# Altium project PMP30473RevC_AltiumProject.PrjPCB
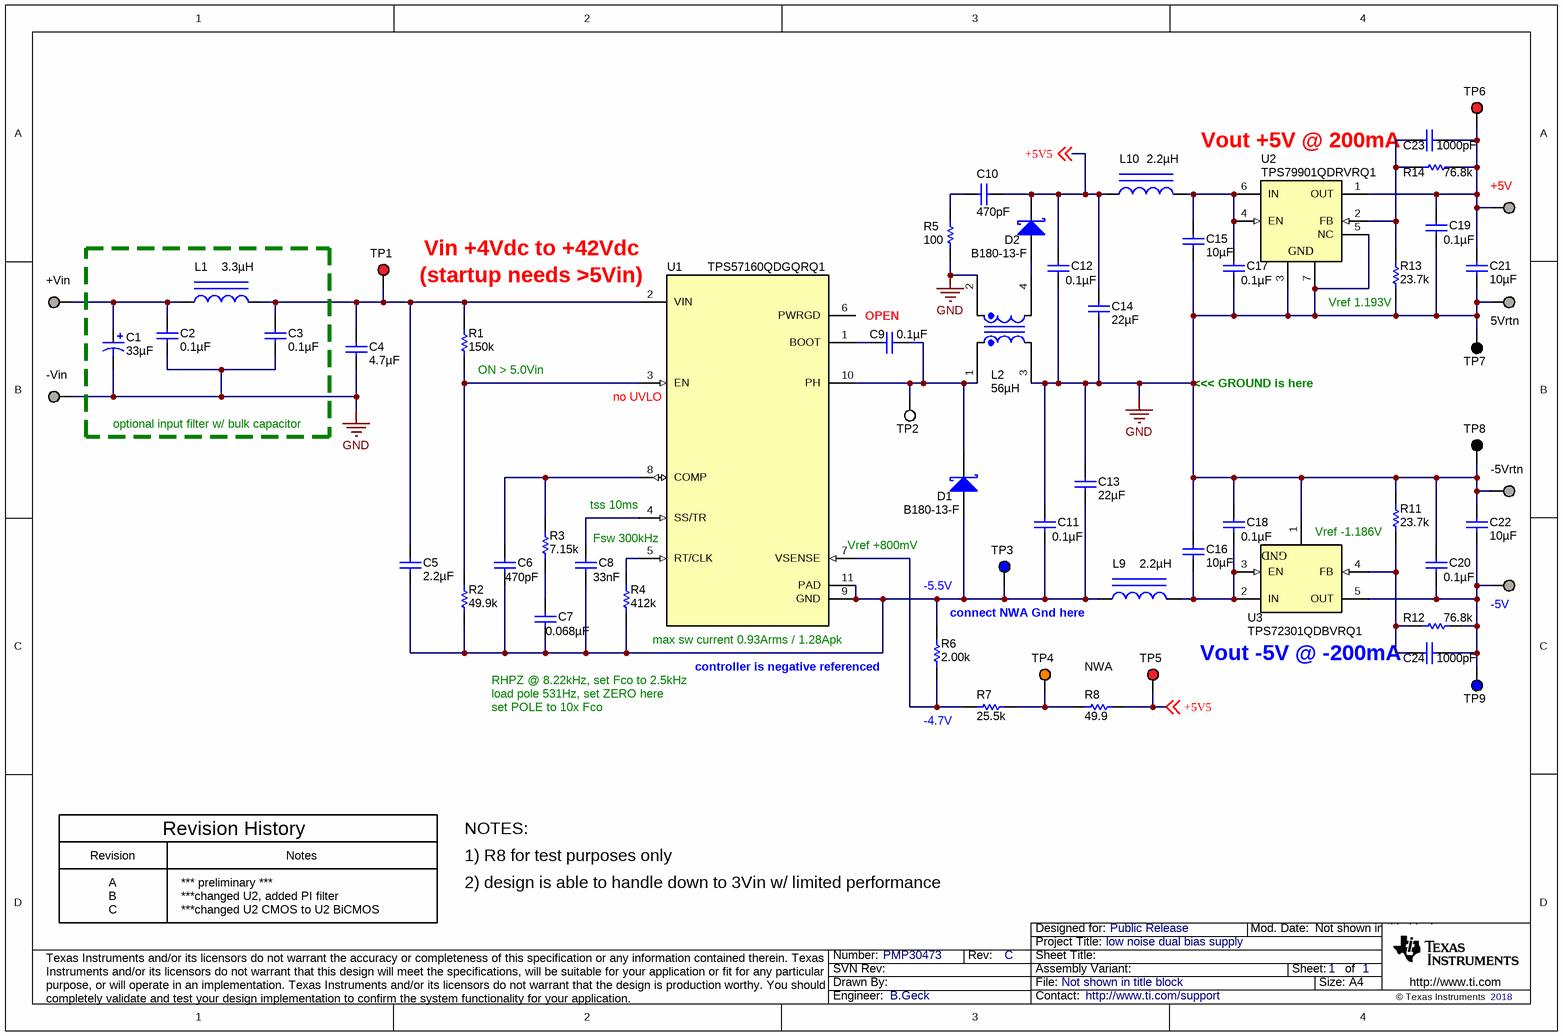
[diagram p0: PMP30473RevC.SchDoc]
CopyrightYear: 2018; PCB_Layout: B.Geck; PCB_Rev: C; PRJ_Customer: Public Release; PRJ_Engineer: B.Geck; PRJ_Number: PMP30473; PRJ_Title: low noise dual bias supply; SCH_Rev: C; TechSupport: http://www.ti.com/support
1 sheet, 60 parts. Net scope: global (net labels, ports and power ports of the same name join across sheets).
Board file: PMP30473RevC_board.PcbDoc

## Sheet PMP30473RevC.SchDoc
size A4; Date: Not shown in title block; ApprovedBy: Not shown in title block; CheckedBy: Not shown in title block; Author: Not shown in title block; CompanyName: Not shown in title block; Engineer: Not shown in title block; Organization: Not shown in title block; Address1: Not shown in title block; Address2: Not shown in title block; Address3: Not shown in title block; Address4: Not shown in title block; DocumentNumber: 1; Revision: Use project parameter SCH_Rev; SheetNumber: 1; SheetTotal: 1; PageSetup: Record=PageOptions¦CenterHorizontal=True¦CenterVertical=True¦PrintScale=0.70¦XCorrection=1.00¦YCorrection=1.00¦PrintKind=0¦BorderSize=5000000¦LeftOffset=0¦BottomOffset=0¦Orientation=2¦PaperLength=1000¦PaperWidth=1000¦Scale=100¦PaperSource=15¦PrintQuality=600¦MediaType=1¦DitherType=10¦PaperKind=A4¦PrintScaleMode=1

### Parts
5Vrtn  Suggest using a net name here  [Keystone1502-2]  (value not drawn)
+5V  Suggest using a net name here  [Keystone1502-2]  (value not drawn)
+Vin  Suggest using a net name here  [Keystone1502-2]  (value not drawn)
-5V  Suggest using a net name here  [Keystone1502-2]  (value not drawn)
-5Vrtn  Suggest using a net name here  [Keystone1502-2]  (value not drawn)
-Vin  Suggest using a net name here  [Keystone1502-2]  (value not drawn)
C1  ValueDisplayed: 33µF  [SM_RADIAL_6.3BMM]  (hidden comment: EEHZC1H330XP)
C2  ValueDisplayed: 0.1µF  [0603]  (hidden comment: GRM188R71H104KA93D)
C3  ValueDisplayed: 0.1µF  [0603]  (hidden comment: GRM188R71H104KA93D)
C4  ValueDisplayed: 4.7µF  [1206_180]  (hidden comment: GRM31CR71H475KA12L)
C5  ValueDisplayed: 2.2µF  [1206_190]  (hidden comment: GRM31CR72A225KA73L)
C6  ValueDisplayed: 470pF  [0603]  (hidden comment: GRM188R71H471KA01D)
C7  ValueDisplayed: 0.068µF  [0603]  (hidden comment: GRM188R71E683KA01D)
C8  ValueDisplayed: 33nF  [0603]  (hidden comment: GRM188R71E333KA01D)
C9  ValueDisplayed: 0.1µF  [0603]  (hidden comment: GRM188R71E104KA01D)
C10  ValueDisplayed: 470pF  [0603]  (hidden comment: GRM188R72A471KA01D)
C11  ValueDisplayed: 0.1µF  [0603]  (hidden comment: GRM188R71H104KA93D)
C12  ValueDisplayed: 0.1µF  [0603]  (hidden comment: GRM188R71H104KA93D)
C13  ValueDisplayed: 22µF  [1206_180]  (hidden comment: GRM31CR71A226KE15L)
C14  ValueDisplayed: 22µF  [1206_180]  (hidden comment: GRM31CR71A226KE15L)
C15  ValueDisplayed: 10µF  [0805_HV]  (hidden comment: GRM21BR71A106KE51K)
C16  ValueDisplayed: 10µF  [0805_HV]  (hidden comment: GRM21BR71A106KE51K)
C17  ValueDisplayed: 0.1µF  [0603]  (hidden comment: GRM188R71H104KA93D)
C18  ValueDisplayed: 0.1µF  [0603]  (hidden comment: GRM188R71H104KA93D)
C19  ValueDisplayed: 0.1µF  [0603]  (hidden comment: GRM188R71H104KA93D)
C20  ValueDisplayed: 0.1µF  [0603]  (hidden comment: GRM188R71H104KA93D)
C21  ValueDisplayed: 10µF  [0805_HV]  (hidden comment: GRM21BR71A106KE51K)
C22  ValueDisplayed: 10µF  [0805_HV]  (hidden comment: GRM21BR71A106KE51K)
C23  ValueDisplayed: 1000pF  [0603]  (hidden comment: GRM188R71E102KA01D)
C24  ValueDisplayed: 1000pF  [0603]  (hidden comment: GRM188R71E102KA01D)
D1  B180-13-F  [SMA]
D2  B180-13-F  [SMA]
L1  ValueDisplayed: 3.3µH  [LPS4012]  (hidden comment: LPS4012-332MLB)
L2  ValueDisplayed: 56µH  [MSD1260]  (hidden comment: MSD1260-563ML)
L9  ValueDisplayed: 2.2µH  [0805_HV]  (hidden comment: LQM21PN2R2MGS)
L10  ValueDisplayed: 2.2µH  [0805_HV]  (hidden comment: LQM21PN2R2MGS)
R1  ValueDisplayed: 150k  [0603]  (hidden comment: CRCW0603150KFKEA)
R2  ValueDisplayed: 49.9k  [0603]  (hidden comment: CRCW060349K9FKEA)
R3  ValueDisplayed: 7.15k  [0603]  (hidden comment: CRCW06037K15FKEA)
R4  ValueDisplayed: 412k  [0603]  (hidden comment: CRCW0603412KFKEA)
R5  ValueDisplayed: 100  [0603]  (hidden comment: CRCW0603100RJNEA)
R6  ValueDisplayed: 2.00k  [0603]  (hidden comment: CRCW06032K00FKEA)
R7  ValueDisplayed: 25.5k  [0603]  (hidden comment: CRCW060325K5FKEA)
R8  ValueDisplayed: 49.9  [0603]  (hidden comment: CRCW060349R9FKEA)
R11  ValueDisplayed: 23.7k  [0603]  (hidden comment: CRCW060323K7FKEA)
R12  ValueDisplayed: 76.8k  [0603]  (hidden comment: CRCW060376K8FKEA)
R13  ValueDisplayed: 23.7k  [0603]  (hidden comment: CRCW060323K7FKEA)
R14  ValueDisplayed: 76.8k  [0603]  (hidden comment: CRCW060376K8FKEA)
TP1  5000  [Keystone5000]  (value not drawn)
TP2  5002  [Keystone5002]  (value not drawn)
TP3  5117  [Keystone5117]  (value not drawn)
TP4  5003  [Keystone5003]  (value not drawn)
TP5  5000  [Keystone5000]  (value not drawn)
TP6  5000  [Keystone5000]  (value not drawn)
TP7  5001  [Keystone5001]  (value not drawn)
TP8  5001  [Keystone5001]  (value not drawn)
TP9  5117  [Keystone5117]  (value not drawn)
U1  TPS57160QDGQRQ1  [DGQ0010D_N]
U2  TPS79901QDRVRQ1  [DRV0006A]
U3  TPS72301QDBVRQ1  [DBV0005A_N]

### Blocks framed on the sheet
optional input filter w/ bulk capacitor: C1-C3 L1

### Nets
GND: 5Vrtn.1 -5Vrtn.1 -Vin.1 C1.2(-) C2.2 C3.2 C4.2 C11.1 C12.2 C13.1 C14.2 C15.2 C16.1 C17.2 C18.1 C19.2 C20.1 C21.2 C22.1 L2.2 L2.3 R5.1 R11.2 R13.1 TP7.1 TP8.1 U2.3(GND) U2.5(NC) U2.7(GND) U3.1(GND)
+5V5: C10.1 C12.1 C14.1 D2.1(K) L10.1 R8.1 TP5.1 ; off-sheet +5V5
Net+5V_1: +5V.1 C19.1 C21.1 C23.1 R14.1 TP6.1 U2.1(OUT)
Net+Vin_1: +Vin.1 C1.1(+) C2.1 L1.1
Net-5V_1: -5V.1 C20.2 C22.2 C24.1 R12.1 TP9.1 U3.5(OUT)
NetC3_1: C3.1 C4.1 C5.1 L1.2 R1.2 TP1.1 U1.2(VIN)
NetC5_2: C5.2 C6.2 C7.2 C8.2 C11.2 C13.2 D1.2(A) L9.1 R2.1 R4.1 R6.2 TP3.1 U1.9(GND) U1.11(PAD)
NetC6_1: C6.1 R3.2 U1.8(COMP)
NetC7_1: C7.1 R3.1
NetC8_1: C8.1 U1.4(SS/TR)
NetC9_1: C9.1 D1.1(K) L2.1 TP2.1 U1.10(PH)
NetC9_2: C9.2 U1.1(BOOT)
NetC10_2: C10.2 R5.2
NetC15_1: C15.1 C17.1 L10.2 U2.4(EN) U2.6(IN)
NetC16_2: C16.2 C18.2 L9.2 U3.2(IN) U3.3(EN)
NetC23_2: C23.2 R13.2 R14.2 U2.2(FB)
NetC24_2: C24.2 R11.1 R12.2 U3.4(FB)
NetD2_2: D2.2(A) L2.4
NetR1_1: R1.1 R2.2 U1.3(EN)
NetR4_2: R4.2 U1.5(RT/CLK)
NetR6_1: R6.1 R7.1 U1.7(VSENSE)
NetR7_2: R7.2 R8.2 TP4.1

Not connected (* = marked no-connect by the designer): U1 6(PWRGD)

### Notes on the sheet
- Vout +5V @ 200mA
- Vin +4Vdc to +42Vdc
- (startup needs >5Vin)
- (near C9) OPEN
- (near R13) Vref 1.193V
- (near R1) ON > 5.0Vin
- <<< GROUND is here
- (near U1) no UVLO !
- (near U1) tss 10ms
- (near U1) Fsw 300kHz
- (near U1) Vref +800mV
- -5.5V
- Vref -1.186V
- max sw current 0.93Arms / 1.28Apk
- connect NWA Gnd here
- Vout -5V @ -200mA
- load pole 531Hz, set ZERO here
- set POLE to 10x Fco
- RHPZ @ 8.22kHz, set Fco to 2.5kHz
- controller is negative referenced
- (near R7) -4.7V
- NWA
- Revision
- Revision History
- Notes
- NOTES:
- 1) R8 for test purposes only
- A
- B
- C
- *** preliminary ***
- ***changed U2, added PI filter
- ***changed U2 CMOS to U2 BiCMOS
- 2) design is able to handle down to 3Vin w/ limited performance

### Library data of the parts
5Vrtn +5V +Vin -5V -5Vrtn -Vin = 1502-2: Terminal, Turret, TH, Double; Manufacturer: Keystone; CompType: Turret Terminal; Green_Lifecycle: Active; Green_REACh: Passed
C1 = EEHZC1H330XP: CAP, Polymer Hybrid, 33 µF, 50 V,+/- 20%, 40 ohm, 6.3x7.7 SMD; Manufacturer: Panasonic; Polarized: Y; CompType: Capacitor; Value: 33uF; U/M: EA; Cap_F: 0.000033; Tolerance_%: 20; Value1: 40 ohm; VDC_V: 50; Value2: 50V; ESR_ohm: 40; IRMS_A: 1.1; TaMin_C: -55; TaMax_C: 125; SizeAreaWB_mm2: 79.98; SizeArea_mm2: 48.18; SizeX_mm: 7.3; SizeY_mm: 6.6; SizeZ_mm: 7.7; AEC Category: Q200; Green_Lifecycle: Active; Green_REACh: Passed
C2 C3 = GRM188R71H104KA93D: CAP, CERM, 0.1 µF, 50 V,+/- 10%, X7R, 0603; Manufacturer: MuRata; Polarized: N; CompType: Capacitor; Value: 0.1uF; U/M: EA; Cap_F: 0.0000001; Tolerance_%: 10; VDC_V: 50; Value2: 50V; TaMin_C: -55; TaMax_C: 125; SizeArea_mm2: 1.28; SizeAreaWB_mm2: 4.68; SizeX_mm: 1.6; SizeY_mm: 0.8; SizeZ_mm: 1; AEC Category: Q200; Green_Lifecycle: Active; Green_REACh: Passed
C4 = GRM31CR71H475KA12L: CAP, CERM, 4.7 µF, 50 V,+/- 10%, X7R, 1206; Manufacturer: MuRata; Polarized: N; CompType: Capacitor; Value: 4.7uF; U/M: EA; Cap_F: 0.0000047; Tolerance_%: 10; VDC_V: 50; Value2: 50V; TaMin_C: -55; TaMax_C: 125; Cap_Case: 1206; SizeArea_mm2: 5.12; SizeAreaWB_mm2: 10.92; SizeX_mm: 3.2; SizeY_mm: 1.6; SizeZ_mm: 1.8; AEC Category: Q200; Green_Lifecycle: Active; Green_REACh: Passed
C5 = GRM31CR72A225KA73L: CAP, CERM, 2.2 µF, 100 V,+/- 10%, X7R, 1206; Manufacturer: MuRata; Polarized: N; CompType: Capacitor; Value: 2.2uF; U/M: EA; Cap_F: 0.0000022; Tolerance_%: 10; VDC_V: 100; Value2: 100V; TaMin_C: -55; TaMax_C: 125; Cap_Case: 1206; SizeArea_mm2: 5.12; SizeAreaWB_mm2: 10.92; SizeX_mm: 3.2; SizeY_mm: 1.6; SizeZ_mm: 1.9; AEC Category: Q200; Green_Lifecycle: Active; Green_REACh: Passed
C6 = GRM188R71H471KA01D: CAP, CERM, 470 pF, 50 V,+/- 10%, X7R, 0603; Manufacturer: MuRata; Polarized: N; CompType: Capacitor; Value: 470pF; U/M: EA; Cap_F: 0.00000000047; Tolerance_%: 10; VDC_V: 50; Value2: 50V; TaMin_C: -55; TaMax_C: 125; SizeArea_mm2: 1.28; SizeAreaWB_mm2: 4.68; SizeX_mm: 1.6; SizeY_mm: 0.8; SizeZ_mm: 1; AEC Category: Q200; Green_Lifecycle: Active; Green_REACh: Passed
C7 = GRM188R71E683KA01D: CAP, CERM, 0.068 µF, 25 V,+/- 10%, X7R, 0603; Manufacturer: MuRata; Polarized: N; CompType: Capacitor; Value: 0.068uF; U/M: EA; Cap_F: 0.000000068; Tolerance_%: 10; VDC_V: 25; Value2: 25V; TaMin_C: -55; TaMax_C: 125; SizeArea_mm2: 1.28; SizeAreaWB_mm2: 4.68; SizeX_mm: 1.6; SizeY_mm: 0.8; SizeZ_mm: 1; AEC Category: Q200; Green_Lifecycle: Active; Green_REACh: Passed
C8 = GRM188R71E333KA01D: CAP, CERM, 0.033 µF, 25 V, +/- 10%, X7R, 0603; Manufacturer: MuRata; Polarized: N; CompType: Capacitor; Value: 0.033uF; U/M: EA; Cap_F: 0.000000033; Tolerance_%: 10; Value1: Unknown; VDC_V: 25; Value2: 25V; TaMin_C: -55; TaMax_C: 125; SizeArea_mm2: 1.28; SizeAreaWB_mm2: 4.68; SizeX_mm: 1.6; SizeY_mm: 0.8; SizeZ_mm: 1; AEC Category: Q200
C9 = GRM188R71E104KA01D: CAP, CERM, 0.1 µF, 25 V, +/- 10%, X7R, 0603; Manufacturer: MuRata; Polarized: N; CompType: Capacitor; Value: 0.1uF; U/M: EA; Cap_F: 0.0000001; Tolerance_%: 10; Value1: Unknown; VDC_V: 25; Value2: 25V; TaMin_C: -55; TaMax_C: 125; SizeArea_mm2: 1.28; SizeAreaWB_mm2: 4.68; SizeX_mm: 1.6; SizeY_mm: 0.8; SizeZ_mm: 1; AEC Category: Q200
C10 = GRM188R72A471KA01D: CAP, CERM, 470 pF, 100 V,+/- 10%, X7R, 0603; Manufacturer: MuRata; Polarized: N; CompType: Capacitor; Value: 470pF; U/M: EA; Cap_F: 0.00000000047; Tolerance_%: 10; VDC_V: 100; Value2: 100V; TaMin_C: -55; TaMax_C: 125; SizeArea_mm2: 1.28; SizeAreaWB_mm2: 4.68; SizeX_mm: 1.6; SizeY_mm: 0.8; SizeZ_mm: 1; AEC Category: Q200
C11 C12 C17-C20 = GRM188R71H104KA93D: CAP, CERM, 0.1 µF, 50 V, +/- 10%, X7R, 0603; Manufacturer: MuRata; Polarized: N; CompType: Capacitor; Value: 0.1uF; U/M: EA; Cap_F: 0.0000001; Tolerance_%: 10; Value1: Unknown; VDC_V: 50; Value2: 50V; TaMin_C: -55; TaMax_C: 125; SizeArea_mm2: 1.28; SizeAreaWB_mm2: 4.68; SizeX_mm: 1.6; SizeY_mm: 0.8; SizeZ_mm: 1; AEC Category: Q200
C13 C14 = GRM31CR71A226KE15L: CAP, CERM, 22 µF, 10 V,+/- 10%, X7R, 1206; Manufacturer: MuRata; Polarized: N; CompType: Capacitor; Value: 22uF; U/M: EA; Cap_F: 0.000022; Tolerance_%: 10; Value2: 10V; TaMin_C: -55; TaMax_C: 125; Cap_Case: 1206; SizeArea_mm2: 5.12; SizeAreaWB_mm2: 10.92; SizeX_mm: 3.2; SizeY_mm: 1.6; SizeZ_mm: 1.8; AEC Category: Q200; Green_Lifecycle: Active; Green_REACh: Passed
C15 C16 C21 C22 = GRM21BR71A106KE51K: CAP, CERM, 10 µF, 10 V,+/- 10%, X7R, 0805; Manufacturer: MuRata; Polarized: N; CompType: Capacitor; Value: 10uF; U/M: EA; Cap_F: 0.00001; Tolerance_%: 10; Value2: 10V; TaMin_C: -55; TaMax_C: 125; Cap_Case: 0805; SizeArea_mm2: 2.5; SizeAreaWB_mm2: 6.75; SizeX_mm: 2; SizeY_mm: 1.25; SizeZ_mm: 1.45; AEC Category: Q200; Green_Lifecycle: Active; Green_REACh: Passed
C23 C24 = GRM188R71E102KA01D: CAP, CERM, 1000 pF, 25 V,+/- 10%, X7R, 0603; Manufacturer: MuRata; Polarized: N; CompType: Capacitor; Value: 1000pF; U/M: EA; Cap_F: 0.000000001; Tolerance_%: 10; VDC_V: 25; Value2: 25V; TaMin_C: -55; TaMax_C: 125; SizeArea_mm2: 1.28; SizeAreaWB_mm2: 4.68; SizeX_mm: 1.6; SizeY_mm: 0.8; SizeZ_mm: 1; AEC Category: Q200; Green_Lifecycle: Active; Green_REACh: Passed
D1 D2 = B180-13-F: Diode, Schottky, 80 V, 1 A, SMA; Manufacturer: Diodes Inc.; U/M: EA; Vf_V: 0.79; Value: 80V; Value1: 1A; Value2: 0.79V; Io_A: 1; Vr_V: 80; TJmax_C: 150; RJC_CperW: 25; SizeAreaWB_mm2: 37.3428; SizeArea_mm2: 16.3228; SizeX_mm: 5.59; SizeY_mm: 2.92; SizeZ_mm: 2.87; AEC Category: Q101; Green_Lifecycle: Not Set; Green_REACh: Incomplete
L1 = LPS4012-332MLB: Inductor, Shielded Drum Core, Ferrite, 3.3 µH, 1.4 A, 0.1 ohm, SMD; Manufacturer: Coilcraft; Value: 3.3uH; Ind_H: 3.3E-6; Imax_A: 1.4; Irms: 2A @ 40C rise; Isat: 1.4A @ 30% inductance drop; DCR_ohm: 0.1; Value1: 0.1 ohm; Value2: 1.4A; SizeAreaWB_mm2: 25; SizeArea_mm2: 16; SizeX_mm: 4; SizeZ_mm: 1.2; AEC Category: Q200; Green_Lifecycle: Not Set; Green_REACh: Incomplete
L2 = MSD1260-563ML: Coupled inductor, 56 µH, 3.07 A, 0.198 ohm, AEC-Q200 Grade 3, TH; Manufacturer: Coilcraft; SymbolCreator: a0412235; SizeAreaWB_mm2: 204.49; SizeArea_mm2: 151.29; SizeX_mm: 12.3; SizeZ_mm: 6.2; Value: 56uH; Ind_H: 56.0E-6; DCR_ohm: 0.198; AEC Category: Q200; AEC Qualified: Y; AEC Grade: 3
L9 L10 = LQM21PN2R2MGS: Inductor, Multilayer, Ferrite, 2.2 µH, 0.95 A, 0.18 ohm, SMD; Manufacturer: MuRata; Value: 2.2uH; Ind_H: 2.2E-6; Imax_A: 0.95; DCR_ohm: 0.18; Value2: 0.95A; SizeAreaWB_mm2: 6.75; SizeArea_mm2: 2.5; SizeX_mm: 2; SizeY_mm: 1.25; SizeZ_mm: 1.45; AEC Category: Q200; Green_Lifecycle: Active; Green_REACh: Passed
R1 = CRCW0603150KFKEA: RES, 150 k, 1%, 0.1 W, 0603; Manufacturer: Vishay-Dale; CompType: Resistor; Value: 150k; Res_ohm: 150000; Tolerance_%: 1; Power_W: 0.1; Value2: 0.1W; VDC_V: 75; TempCo: 100 ppm/C; SizeArea_mm2: 1.28; SizeX_mm: 1.6; SizeY_mm: 0.8; EIA_Code: E96; U/M: EA; AEC Category: Q200; Green_Lifecycle: Active; Green_REACh: Passed
R2 = CRCW060349K9FKEA: RES, 49.9 k, 1%, 0.1 W, 0603; Manufacturer: Vishay-Dale; CompType: Resistor; Value: 49.9k; Res_ohm: 49900; Value_Code: 49k9; Tolerance_%: 1; Power_W: 0.1; Value2: 0.1W; VDC_V: 75; TempCo: 100 ppm/C; SizeArea_mm2: 1.28; SizeX_mm: 1.6; SizeY_mm: 0.8; EIA_Code: E96; U/M: EA; AEC Category: Q200; Green_Lifecycle: Active; Green_REACh: Passed
R3 = CRCW06037K15FKEA: RES, 7.15 k, 1%, 0.1 W, 0603; Manufacturer: Vishay-Dale; CompType: Resistor; Value: 7.15k; Res_ohm: 7150; Value_Code: 7k15; Tolerance_%: 1; Power_W: 0.1; Value2: 0.1W; VDC_V: 75; TempCo: 100 ppm/C; SizeArea_mm2: 1.28; SizeX_mm: 1.6; SizeY_mm: 0.8; EIA_Code: E96; U/M: EA; AEC Category: Q200; Green_Lifecycle: Active; Green_REACh: Passed
R4 = CRCW0603412KFKEA: RES, 412 k, 1%, 0.1 W, 0603; Manufacturer: Vishay-Dale; CompType: Resistor; Value: 412k; Res_ohm: 412000; Tolerance_%: 1; Power_W: 0.1; Value2: 0.1W; VDC_V: 75; TempCo: 100 ppm/C; SizeArea_mm2: 1.28; SizeX_mm: 1.6; SizeY_mm: 0.8; EIA_Code: E96; U/M: EA; AEC Category: Q200
R5 = CRCW0603100RJNEA: RES, 100, 5%, 0.1 W, 0603; Manufacturer: Vishay-Dale; CompType: Resistor; Value: 100; Value_Code: 100R; Tolerance_%: 5; Power_W: 0.1; Value2: 0.1W; VDC_V: 75; TempCo: 200 ppm/C; SizeArea_mm2: 1.28; SizeX_mm: 1.6; SizeY_mm: 0.8; SizeZ_mm: 1; EIA_Code: E24; U/M: EA; AEC Category: Q200; Green_Lifecycle: Active; Green_REACh: Passed
R6 = CRCW06032K00FKEA: RES, 2.00 k, 1%, 0.1 W, 0603; Manufacturer: Vishay-Dale; CompType: Resistor; Value: 2.00k; Res_ohm: 2000; Value_Code: 2k00; Tolerance_%: 1; Power_W: 0.1; Value2: 0.1W; VDC_V: 75; TempCo: 100 ppm/C; SizeArea_mm2: 1.28; SizeX_mm: 1.6; SizeY_mm: 0.8; EIA_Code: E96; U/M: EA; AEC Category: Q200; Green_Lifecycle: Active; Green_REACh: Passed
R7 = CRCW060325K5FKEA: RES, 25.5 k, 1%, 0.1 W, 0603; Manufacturer: Vishay-Dale; CompType: Resistor; Value: 25.5k; Res_ohm: 25500; Value_Code: 25k5; Tolerance_%: 1; Power_W: 0.1; Value2: 0.1W; VDC_V: 75; TempCo: 100 ppm/C; SizeArea_mm2: 1.28; SizeX_mm: 1.6; SizeY_mm: 0.8; EIA_Code: E96; U/M: EA; AEC Category: Q200; Green_Lifecycle: Active; Green_REACh: Passed
R8 = CRCW060349R9FKEA: RES, 49.9, 1%, 0.1 W, 0603; Manufacturer: Vishay-Dale; CompType: Resistor; Value: 49.9; Value_Code: 49R9; Tolerance_%: 1; Power_W: 0.1; Value2: 0.1W; VDC_V: 75; TempCo: 100 ppm/C; SizeArea_mm2: 1.28; SizeX_mm: 1.6; SizeY_mm: 0.8; EIA_Code: E96; U/M: EA; AEC Category: Q200
R11 R13 = CRCW060323K7FKEA: RES, 23.7 k, 1%, 0.1 W, 0603; Manufacturer: Vishay-Dale; CompType: Resistor; Value: 23.7k; Res_ohm: 23700; Value_Code: 23k7; Tolerance_%: 1; Power_W: 0.1; Value2: 0.1W; VDC_V: 75; TempCo: 100 ppm/C; SizeArea_mm2: 1.28; SizeX_mm: 1.6; SizeY_mm: 0.8; EIA_Code: E96; U/M: EA; AEC Category: Q200
R12 R14 = CRCW060376K8FKEA: RES, 76.8 k, 1%, 0.1 W, 0603; Manufacturer: Vishay-Dale; CompType: Resistor; Value: 76.8k; Res_ohm: 76800; Value_Code: 76k8; Tolerance_%: 1; Power_W: 0.1; Value2: 0.1W; VDC_V: 75; TempCo: 100 ppm/C; SizeArea_mm2: 1.28; SizeX_mm: 1.6; SizeY_mm: 0.8; EIA_Code: E96; U/M: EA; AEC Category: Q200; Green_Lifecycle: Active; Green_REACh: Passed
TP1 TP5 TP6 = 5000: Test Point, Miniature, Red, TH; Manufacturer: Keystone; CompType: Test Point Loop; U/M: EA
TP2 = 5002: Test Point, Miniature, White, TH; Manufacturer: Keystone; CompType: Test Point Loop; ContactFinish: Silver; Green_Lifecycle: Active; Green_REACh: Passed
TP3 TP9 = 5117: Test Point, Miniature, Blue, TH; Manufacturer: Keystone; CompType: Test Point Loop; U/M: EA; ContactFinish: Silver; Green_Lifecycle: Active; Green_REACh: Passed
TP4 = 5003: Test Point, Miniature, Orange, TH; Manufacturer: Keystone; CompType: Test Point Loop; U/M: EA
TP7 TP8 = 5001: Test Point, Miniature, Black, TH; Manufacturer: Keystone; CompType: Test Point Loop; ContactFinish: Silver; Green_Lifecycle: Active; Green_REACh: Passed
U1 = TPS57160QDGQRQ1: Automotive 3.5V to 60V, 1.5A Step Down SWIFT(TM) Converter with Eco-Mode(TM), DGQ0010D (VSSOP-10); Manufacturer: Texas Instruments; SymbolCreator: a0411947; SizeArea_mm2: 14.7; SizeAreaWB_mm2: 23.6; SizeX_mm: 4.9; SizeY_mm: 3; SizeZ_mm: 1.1; CompType: IC; U/M: EA
U2 = TPS79901QDRVRQ1: Single Output High PSRR LDO, 200 mA, Adjustable 1.2 to 6.5 V Output, 2.7 to 6.5 V Input, with Low IQ, 6-pin SON (DRV), -40 to 125 degC, Green (RoHS & no Sb/Br); Manufacturer: Texas Instruments; Alternate PartNumber: Equivalent; Accuracy(%): 2; Iout(Max)(A): 0.2; Iq(Typ)(mA): 0.04; Rating: Automotive; SubFamily: Single Channel LDO; Vdo(Typ)(mV): 90; Vin(Max)(V): 6.5; Vin(Min)(V): 2.7; Vout Adj(Min)(V): 1.2
U3 = TPS72301QDBVRQ1: Single Output High PSRR LDO, 200 mA, Adjustable -10 to -1.2 V Output, -10 to -2.7 V Input, 5-pin SOT-23 (DBV), -40 to 125 degC, Green (RoHS & no Sb/Br); Manufacturer: Texas Instruments; Alternate PartNumber: Equivalent; Accuracy(%): 2; Iout(Max)(A): 0.2; Iq(Typ)(mA): 0.13; SubFamily: Single Channel LDO; Vdo(Typ)(mV): 280

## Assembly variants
001: all parts fitted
